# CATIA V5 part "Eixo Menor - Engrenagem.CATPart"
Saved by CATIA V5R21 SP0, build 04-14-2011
Part number: Eixo Menor - Engrenagem
Definition: Eixo Menor - Engrenagem
Nomenclature: Eixo Médio - Engrenagem
Source: Unknown
Bounding box of the stored display mesh (mm): x -0.45 to 0.45, y 0 to 5.6, z -0.45 to 0.45
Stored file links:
  C:\Users\beatr\OneDrive\Documents\UNB\2026_1\Pi1\Componentes eletronicos\Eixo Menor - Engrenagem.CATPart
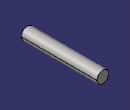
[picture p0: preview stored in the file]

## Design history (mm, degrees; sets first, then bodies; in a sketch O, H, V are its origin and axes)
Body1 "Sólido1" (main body)
  Solid1: solid without history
